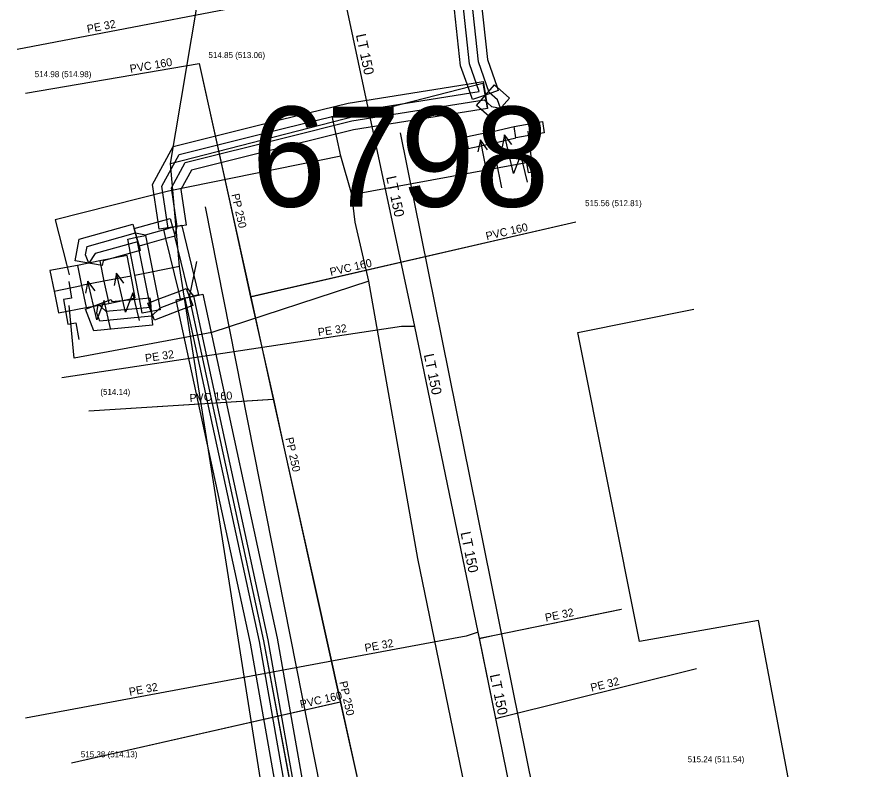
# Model space of a CAD drawing. Extents: x -668867 to -667827, y -1131943 to -1131019.
# Drawn here: x -668382.18 to -668363.35, y -1131408.59 to -1131392.08 of the extents above; entities that cross this region are included whole.
import ezdxf

# ---------------------------------------------------------------- set-up
doc = ezdxf.new("R2010")
doc.units = 0
for name, color, linetype in [('G_Budovy_Objekty', 7, 'Continuous'), ('G_Plochy_zpevnene', 7, 'Continuous'), ('G_Site-Rozvadece', 7, 'Continuous'), ('G_Z_CHRANICKA-TEPLOVOD_kotovane', 7, 'Continuous'), ('G_Z_ELsilove_podz_kotovane', 7, 'Continuous'), ('G_Z_KANAL_podz_kotovane', 7, 'Continuous'), ('G_Z_PLYNY_podz_geodeticky', 7, 'Continuous'), ('G_Z_SPOJE_podz_kotovane', 7, 'Continuous'), ('G_Z_VODA_podz_kotovane', 7, 'Continuous'), ('Vrstva 1', 7, 'Continuous'), ('Vrstva 11', 7, 'Continuous'), ('Vrstva 18', 7, 'Continuous'), ('Vrstva 2', 7, 'Continuous'), ('Vrstva 26', 7, 'Continuous'), ('Vrstva 3', 7, 'Continuous'), ('Vrstva 4', 7, 'Continuous'), ('Vrstva 6', 7, 'Continuous'), ('Vrstva 8', 7, 'Continuous')]:
    doc.layers.add(name, color=color, linetype=linetype)

msp = doc.modelspace()

# ---------------------------------------------------------------- linework, layer by layer
at = {"layer": 'G_Budovy_Objekty'}
for p, q in [((-668369.88, -1131399), (-668367.34, -1131398.49)), ((-668368.53, -1131405.78), (-668369.88, -1131399)), ((-668365.92, -1131405.32), (-668368.53, -1131405.78)), ((-668364.22, -1131414.33), (-668365.92, -1131405.32))]:
    msp.add_line(p, q, dxfattribs=at)
at = {"layer": 'G_Plochy_zpevnene'}
for p, q in [((-668369.5, -1131415.79), (-668373.77, -1131394.62)), ((-668378.06, -1131396.24), (-668373.51, -1131419.22))]:
    msp.add_line(p, q, dxfattribs=at)
at = {"layer": 'G_Site-Rozvadece'}
for p, q in [((-668371.75, -1131394.59), (-668371.28, -1131394.48)), ((-668371.7, -1131394.84), (-668371.24, -1131394.73)), ((-668371.49, -1131394.66), (-668371.541, -1131394.924)), ((-668371.291, -1131395.512), (-668371.49, -1131394.66)), ((-668371.327, -1131394.873), (-668371.49, -1131394.66)), ((-668372.02, -1131394.77), (-668372.079, -1131395.032)), ((-668371.846, -1131395.627), (-668372.02, -1131394.77)), ((-668371.863, -1131394.988), (-668372.02, -1131394.77)), ((-668371.133, -1131395.09), (-668371.291, -1131395.512)), ((-668370.99, -1131395.699), (-668371.133, -1131395.09)), ((-668371.675, -1131395.21), (-668371.846, -1131395.627)), ((-668371.551, -1131395.824), (-668371.675, -1131395.21)), ((-668380.37, -1131397.43), (-668380.86, -1131397.53)), ((-668380, -1131397.7), (-668380.051, -1131397.964)), ((-668379.801, -1131398.552), (-668380, -1131397.7)), ((-668379.837, -1131397.913), (-668380, -1131397.7)), ((-668380.63, -1131397.87), (-668380.681, -1131398.134)), ((-668380.431, -1131398.722), (-668380.63, -1131397.87)), ((-668380.467, -1131398.083), (-668380.63, -1131397.87)), ((-668381.37, -1131398.09), (-668380.77, -1131397.97)), ((-668379.643, -1131398.13), (-668379.801, -1131398.552)), ((-668379.5, -1131398.739), (-668379.643, -1131398.13)), ((-668380.273, -1131398.3), (-668380.431, -1131398.722)), ((-668380.13, -1131398.909), (-668380.273, -1131398.3)), ((-668380.67, -1131398.45), (-668380.17, -1131398.36))]:
    msp.add_line(p, q, dxfattribs=at)
for points in [[(-668371.28, -1131394.48), (-668370.66, -1131394.37), (-668370.62, -1131394.62), (-668371.24, -1131394.73), (-668371.28, -1131394.48)], [(-668370.95, -1131394.55), (-668370.887, -1131394.913), (-668371.067, -1131394.945), (-668370.971, -1131395.488), (-668370.79, -1131395.457), (-668370.725, -1131395.819)], [(-668371.75, -1131394.59), (-668372.34, -1131394.71), (-668372.29, -1131394.96), (-668371.7, -1131394.84), (-668371.75, -1131394.59)], [(-668380.17, -1131398.36), (-668379.59, -1131398.24), (-668379.68, -1131397.76), (-668379.77, -1131397.31), (-668380.37, -1131397.43)], [(-668380.86, -1131397.53), (-668381.46, -1131397.64), (-668381.37, -1131398.09), (-668381.27, -1131398.57), (-668380.67, -1131398.45)], [(-668380.86, -1131397.53), (-668380.77, -1131397.97), (-668380.67, -1131398.45)], [(-668380.37, -1131397.43), (-668380.28, -1131397.87), (-668380.17, -1131398.36)], [(-668379.68, -1131397.76), (-668380.28, -1131397.87), (-668380.77, -1131397.97)], [(-668381.05, -1131397.88), (-668380.986, -1131398.242), (-668381.167, -1131398.274), (-668381.07, -1131398.818), (-668380.89, -1131398.787), (-668380.825, -1131399.149)]]:
    msp.add_lwpolyline(points, dxfattribs=at)
at = {"layer": 'G_Z_CHRANICKA-TEPLOVOD_kotovane'}
for points in [[(-668372.312, -1131393.55), (-668372.455, -1131393.147), (-668372.697, -1131390.886), (-668374.295, -1131383.097), (-668375.698, -1131375.4), (-668374.961, -1131374.359), (-668374.652, -1131373.694), (-668374.108, -1131373.946), (-668374.439, -1131374.661), (-668375.062, -1131375.54), (-668373.705, -1131382.983), (-668372.103, -1131390.794), (-668371.865, -1131393.013), (-668371.653, -1131393.616), (-668371.627, -1131393.69), (-668371.91, -1131393.79), (-668372.193, -1131393.89)], [(-668372.312, -1131393.55), (-668371.957, -1131393.494), (-668371.91, -1131393.79), (-668371.863, -1131394.086), (-668372.002, -1131394.108), (-668374.8, -1131394.554), (-668376.248, -1131394.911), (-668378.359, -1131395.439), (-668378.589, -1131395.865), (-668378.473, -1131396.646), (-668378.571, -1131396.661), (-668378.77, -1131396.69), (-668379.067, -1131396.734), (-668379.091, -1131396.572), (-668379.211, -1131395.755), (-668378.761, -1131394.921), (-668376.392, -1131394.329), (-668374.92, -1131393.966)], [(-668371.712, -1131393.565), (-668371.653, -1131393.616), (-668371.382, -1131393.855), (-668371.778, -1131394.305), (-668372.002, -1131394.108), (-668372.108, -1131394.015), (-668371.91, -1131393.79)], [(-668379.695, -1131397.259), (-668380.297, -1131397.428), (-668380.314, -1131397.531), (-668380.906, -1131397.429), (-668380.823, -1131396.952), (-668379.641, -1131396.621), (-668379.563, -1131396.9), (-668379.56, -1131396.91), (-668379.506, -1131397.103), (-668379.479, -1131397.199)], [(-668379.091, -1131396.572), (-668378.824, -1131396.497), (-668378.77, -1131396.69), (-668378.716, -1131396.883), (-668378.916, -1131396.938), (-668379.328, -1131397.053), (-668379.506, -1131397.103), (-668379.506, -1131397.103), (-668379.56, -1131396.91), (-668379.563, -1131396.9), (-668379.614, -1131396.717)], [(-668378.576, -1131396.643), (-668378.571, -1131396.661), (-668378.206, -1131398.173), (-668378.4, -1131398.22), (-668378.594, -1131398.267), (-668378.596, -1131398.262), (-668378.636, -1131398.096), (-668378.916, -1131396.938), (-668378.964, -1131396.737), (-668378.77, -1131396.69)], [(-668379.364, -1131396.871), (-668379.328, -1131397.053), (-668379.089, -1131398.269), (-668379.044, -1131398.501), (-668379.24, -1131398.54), (-668379.436, -1131398.578), (-668379.498, -1131398.263), (-668379.695, -1131397.259), (-668379.756, -1131396.948), (-668379.56, -1131396.91)], [(-668378.636, -1131398.096), (-668378.471, -1131398.033), (-668378.4, -1131398.22), (-668378.329, -1131398.407), (-668378.641, -1131398.526), (-668379.169, -1131398.727), (-668379.24, -1131398.54), (-668379.311, -1131398.353), (-668379.259, -1131398.333), (-668379.089, -1131398.269)], [(-668379.498, -1131398.263), (-668379.268, -1131398.241), (-668379.259, -1131398.333), (-668379.24, -1131398.54), (-668379.212, -1131398.839), (-668380.498, -1131398.96), (-668380.68, -1131398.488), (-668380.12, -1131398.272), (-668380.102, -1131398.32)], [(-668378.107, -1131398.157), (-668376.476, -1131405.702), (-668375.385, -1131411.878), (-668375.678, -1131411.93), (-668375.68, -1131411.93), (-668375.975, -1131411.982), (-668376.025, -1131411.703), (-668377.064, -1131405.818), (-668378.641, -1131398.526), (-668378.693, -1131398.283), (-668378.596, -1131398.262), (-668378.4, -1131398.22)]]:
    msp.add_lwpolyline(points, close=True, dxfattribs=at)
at = {"layer": 'G_Z_ELsilove_podz_kotovane'}
for points in [[(-668375.794, -1131411.854), (-668376.868, -1131405.779), (-668378.495, -1131398.256), (-668379.051, -1131398.468), (-668379.231, -1131398.64), (-668380.366, -1131398.747), (-668380.432, -1131398.575), (-668380.4, -1131398.38), (-668380.234, -1131398.533), (-668379.259, -1131398.441), (-668379.541, -1131397.008), (-668380.472, -1131397.269), (-668380.61, -1131397.48), (-668380.68, -1131397.295), (-668380.648, -1131397.111), (-668379.587, -1131396.814), (-668379.367, -1131396.856), (-668378.867, -1131396.717), (-668379.004, -1131395.792), (-668378.627, -1131395.094), (-668376.344, -1131394.523), (-668374.88, -1131394.162), (-668372.044, -1131393.71), (-668372.258, -1131393.102), (-668372.499, -1131390.855)], [(-668375.585, -1131411.895), (-668376.672, -1131405.741), (-668378.302, -1131398.199), (-668378.447, -1131398.024), (-668378.723, -1131396.885), (-668378.671, -1131396.675), (-668378.796, -1131395.828), (-668378.493, -1131395.266), (-668376.296, -1131394.717), (-668374.84, -1131394.358), (-668371.94, -1131393.896), (-668371.774, -1131394.043), (-668371.58, -1131394.08), (-668371.642, -1131393.893), (-668371.825, -1131393.732), (-668372.062, -1131393.058), (-668372.301, -1131390.825)], [(-668374.41, -1131418.54), (-668374.6, -1131417.38), (-668376.77, -1131405.76), (-668378.4, -1131398.22), (-668378.24, -1131397.44)]]:
    msp.add_lwpolyline(points, dxfattribs=at)
at = {"layer": 'G_Z_KANAL_podz_kotovane'}
for p, q in [((-668382, -1131393.75), (-668378.19, -1131393.1)), ((-668369.93, -1131396.58), (-668377.06, -1131398.22)), ((-668380.61, -1131400.72), (-668376.56, -1131400.46)), ((-668380.99, -1131408.44), (-668375.09, -1131407.1))]:
    msp.add_line(p, q, dxfattribs=at)
msp.add_lwpolyline([(-668378.19, -1131393.1), (-668377.53, -1131396.07), (-668377.06, -1131398.22), (-668376.82, -1131399.29), (-668376.56, -1131400.46), (-668376.32, -1131401.58), (-668375.63, -1131404.66), (-668375.09, -1131407.1), (-668374.62, -1131409.23), (-668374.29, -1131410.75), (-668373.97, -1131412.17), (-668373.46, -1131414.47), (-668372.81, -1131417.42), (-668372.33, -1131419.6)], dxfattribs=at)
at = {"layer": 'G_Z_PLYNY_podz_geodeticky'}
for points in [[(-668364.23, -1131449.36), (-668365.15, -1131447.54), (-668365.63, -1131443.81), (-668366.45, -1131439.11), (-668366.86, -1131436.78), (-668367.03, -1131435.83), (-668367.2, -1131434.95), (-668367.69, -1131432.4), (-668368.64, -1131427.56), (-668368.96, -1131425.61), (-668369.46, -1131422.64), (-668370.15, -1131418.54), (-668370.61, -1131416.76), (-668371.17, -1131413.83), (-668371.67, -1131411.76), (-668372.41, -1131408.72), (-668373.39, -1131403.96), (-668374.47, -1131397.87), (-668374.77, -1131396.58), (-668374.84, -1131395.97), (-668375.08, -1131395.13), (-668375.27, -1131394.25)], [(-668374.84, -1131395.97), (-668370.89, -1131395.25), (-668370.97, -1131394.58)], [(-668375.08, -1131395.13), (-668378.86, -1131395.9), (-668381.35, -1131396.53), (-668381.1, -1131397.5), (-668381.04, -1131397.73)], [(-668374.47, -1131397.87), (-668377.91, -1131399), (-668380.93, -1131399.56), (-668381.02, -1131398.64), (-668381.04, -1131398.41)]]:
    msp.add_lwpolyline(points, dxfattribs=at)
at = {"layer": 'G_Z_SPOJE_podz_kotovane'}
for points in [[(-668378.82, -1131395.29), (-668375.34, -1131374.62)], [(-668378.82, -1131395.29), (-668371.97, -1131393.53), (-668371.87, -1131394.07)], [(-668378.62, -1131397.55), (-668378.82, -1131395.29)], [(-668378.62, -1131397.55), (-668379.6, -1131397.75)], [(-668376.47, -1131411.17), (-668378.62, -1131397.55)]]:
    msp.add_lwpolyline(points, dxfattribs=at)
at = {"layer": 'G_Z_VODA_podz_kotovane'}
for points in [[(-668362.72, -1131454.38), (-668362.92, -1131452.82), (-668364.67, -1131444.16), (-668365.58, -1131439.63), (-668366.38, -1131435.35), (-668367.09, -1131431.58), (-668368.16, -1131426.31), (-668368.17, -1131426.28), (-668369.18, -1131420.47), (-668369.48, -1131419.1), (-668369.82, -1131417.18), (-668370.72, -1131412.17), (-668371.68, -1131407.47), (-668372.04, -1131405.71), (-668372.07, -1131405.57), (-668373.46, -1131398.87), (-668375.07, -1131391.32), (-668377.42, -1131377.46), (-668377.7, -1131376.11)], [(-668375.07, -1131391.32), (-668375.23, -1131391.45), (-668382.18, -1131392.79)], [(-668373.46, -1131398.87), (-668373.63, -1131398.87), (-668373.75, -1131398.87), (-668381.2, -1131399.99)], [(-668372.04, -1131405.71), (-668371.71, -1131405.64), (-668368.93, -1131405.07)], [(-668372.07, -1131405.57), (-668372.33, -1131405.66), (-668372.61, -1131405.71), (-668382, -1131407.46)], [(-668371.68, -1131407.47), (-668371.54, -1131407.43), (-668367.28, -1131406.37)]]:
    msp.add_lwpolyline(points, dxfattribs=at)
at = {"layer": 'Vrstva 1'}
for p, q in [((-668378.4, -1131398.22), (-668378.24, -1131397.44)), ((-668378.24, -1131397.44), (-668378.24, -1131397.44)), ((-668376.77, -1131405.76), (-668378.4, -1131398.22)), ((-668374.6, -1131417.38), (-668376.77, -1131405.76))]:
    msp.add_line(p, q, dxfattribs=at)
at = {"layer": 'Vrstva 11'}
msp.add_lwpolyline([(-668378.19, -1131393.1), (-668377.533, -1131396.069), (-668377.058, -1131398.216), (-668376.821, -1131399.293), (-668376.562, -1131400.462), (-668376.315, -1131401.577), (-668375.634, -1131404.66), (-668375.094, -1131407.102), (-668374.623, -1131409.229), (-668374.286, -1131410.754), (-668373.972, -1131412.175), (-668373.463, -1131414.474), (-668372.813, -1131417.417), (-668372.33, -1131419.6)], dxfattribs=at)
at = {"layer": 'Vrstva 18'}
for p, q in [((-668382, -1131393.75), (-668378.19, -1131393.1)), ((-668369.93, -1131396.58), (-668377.058, -1131398.216)), ((-668380.61, -1131400.72), (-668376.562, -1131400.462)), ((-668380.99, -1131408.44), (-668375.094, -1131407.102))]:
    msp.add_line(p, q, dxfattribs=at)
at = {"layer": 'Vrstva 26'}
for points in [[(-668362.72, -1131454.38), (-668362.92, -1131452.82), (-668364.667, -1131444.156), (-668365.58, -1131439.63), (-668366.382, -1131435.355), (-668367.09, -1131431.58), (-668368.163, -1131426.312), (-668368.17, -1131426.28), (-668369.18, -1131420.47), (-668369.48, -1131419.1), (-668369.823, -1131417.183), (-668370.72, -1131412.17), (-668371.682, -1131407.465), (-668372.042, -1131405.708), (-668372.07, -1131405.57), (-668373.46, -1131398.87), (-668375.07, -1131391.32), (-668377.42, -1131377.46), (-668377.7, -1131376.11)], [(-668375.07, -1131391.32), (-668375.23, -1131391.45), (-668382.18, -1131392.79)], [(-668373.46, -1131398.87), (-668373.629, -1131398.87), (-668373.75, -1131398.87), (-668381.2, -1131399.99)], [(-668372.042, -1131405.708), (-668371.711, -1131405.64), (-668368.928, -1131405.066)], [(-668372.07, -1131405.57), (-668372.33, -1131405.66), (-668372.613, -1131405.713), (-668382, -1131407.46)], [(-668371.682, -1131407.465), (-668371.54, -1131407.43), (-668367.28, -1131406.37)]]:
    msp.add_lwpolyline(points, dxfattribs=at)
at = {"layer": 'Vrstva 6'}
for p, q in [((-668373.75, -1131398.87), (-668373.75, -1131398.87)), ((-668372.33, -1131405.66), (-668372.33, -1131405.66)), ((-668371.711, -1131405.64), (-668371.711, -1131405.64)), ((-668371.54, -1131407.43), (-668371.54, -1131407.43))]:
    msp.add_line(p, q, dxfattribs=at)
at = {"layer": 'Vrstva 8'}
for p, q in [((-668378.19, -1131393.1), (-668378.19, -1131393.1)), ((-668382, -1131393.75), (-668382, -1131393.75)), ((-668369.93, -1131396.58), (-668369.93, -1131396.58)), ((-668380.61, -1131400.72), (-668380.61, -1131400.72)), ((-668380.99, -1131408.44), (-668380.99, -1131408.44))]:
    msp.add_line(p, q, dxfattribs=at)

# ---------------------------------------------------------------- texts
at = {"layer": 'Vrstva 2'}
for s, height, p in [('514.85 (513.06)', 0.13163, (-668377.985, -1131392.978)), ('514.98 (514.98)', 0.13163, (-668381.795, -1131393.397)), ('515.56 (512.81)', 0.13163, (-668369.724, -1131396.227)), ('\xa0(514.14)', 0.1316, (-668380.405, -1131400.367)), ('515.38 (514.13)', 0.13163, (-668380.785, -1131408.318)), ('515.24 (511.54)', 0.13163, (-668367.474, -1131408.427))]:
    msp.add_text(s, height=height, dxfattribs=at).set_placement(p)
at = {"layer": 'Vrstva 3'}
for s, rotation, p in [('PVC 160', 9.6749, (-668379.694, -1131393.303)), ('PP 250', 282.502, (-668377.482, -1131395.971)), ('PVC 160', 12.9067, (-668371.88, -1131396.974)), ('PVC 160', 12.9475, (-668375.302, -1131397.759)), ('PVC 160', 3.6421, (-668378.394, -1131400.526)), ('PP 250', 282.4529, (-668376.299, -1131401.319)), ('PP 250', 282.4931, (-668375.117, -1131406.667)), ('PVC 160', 12.7741, (-668375.956, -1131407.244))]:
    msp.add_text(s, height=0.1755, rotation=rotation, dxfattribs=at).set_placement(p)
at = {"layer": 'Vrstva 4'}
for s, height, rotation, p in [('PE 32', 0.1755, 10.9082, (-668380.632, -1131392.429)), ('LT 150', 0.2194, 282.0257, (-668374.752, -1131392.47)), ('LT 150', 0.2194, 282.0221, (-668374.087, -1131395.588)), ('PE 32', 0.1755, 8.5827, (-668375.571, -1131399.081)), ('PE 32', 0.1755, 8.558, (-668379.361, -1131399.651)), ('LT 150', 0.2194, 281.6341, (-668373.261, -1131399.488)), ('LT 150', 0.2194, 281.6042, (-668372.457, -1131403.391)), ('PE 32', 0.1755, 11.5991, (-668370.583, -1131405.344)), ('PE 32', 0.1755, 10.5306, (-668374.542, -1131406.009)), ('LT 150', 0.2194, 281.6341, (-668371.814, -1131406.513)), ('PE 32', 0.1755, 13.9877, (-668369.581, -1131406.88)), ('PE 32', 0.1755, 10.506, (-668379.711, -1131406.971))]:
    msp.add_text(s, height=height, rotation=rotation, dxfattribs=at).set_placement(p)
msp.add_text('6798', height=2.1939, dxfattribs=at).set_placement((-668377.037, -1131396.239))

doc.saveas('drawing.dxf')
